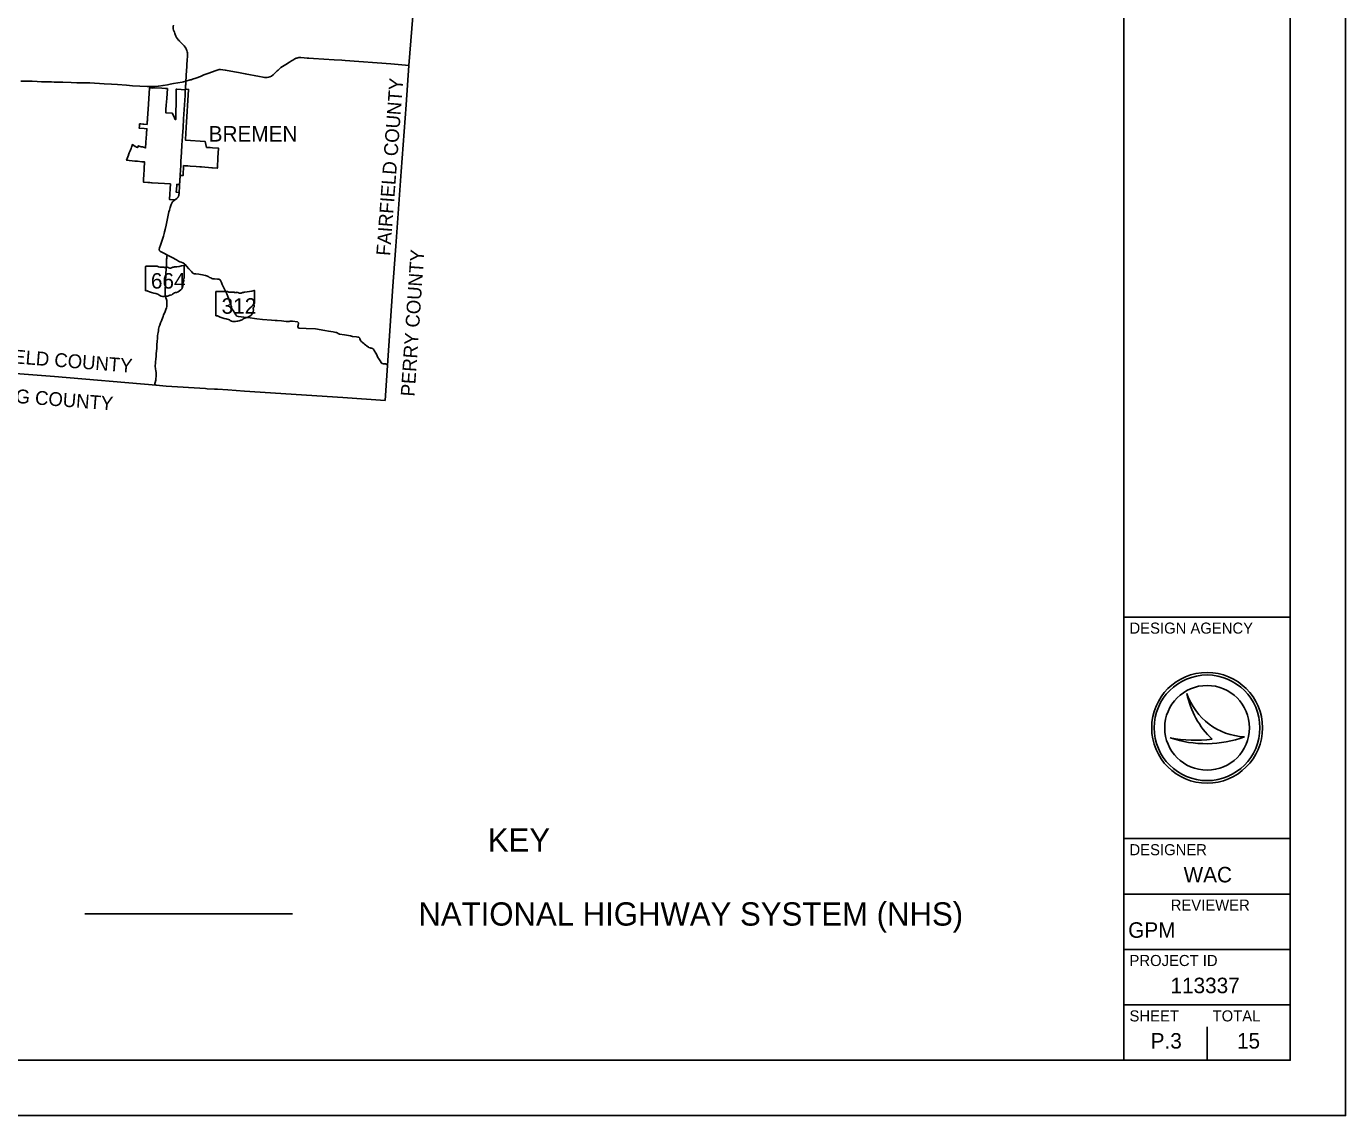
# Model space of a CAD drawing. Extents: x 1801177 to 2073177, y 551183 to 727183.
# Drawn here: x 1977949 to 2073177, y 551183 to 629829 of the extents above; entities that cross this region are included whole.
import ezdxf

# ---------------------------------------------------------------- set-up
doc = ezdxf.new("R2010")
doc.units = 0
for name, color, linetype in [('GM_X_Corporation', 7, 'Continuous'), ('GM_X_Corporation_Text', 7, 'Continuous'), ('GM_X_County', 7, 'Continuous'), ('GM_X_County_Text', 7, 'Continuous'), ('GM_X_State_Location', 7, 'Continuous'), ('GM_X_State_Route', 7, 'Continuous'), ('GM_X_State_Shield', 7, 'Continuous'), ('SH_Border', 7, 'Continuous'), ('SH_Cut_Line', 7, 'Continuous'), ('SH_Data', 7, 'Continuous'), ('UT_P_Electric', 7, 'Continuous')]:
    doc.layers.add(name, color=color, linetype=linetype)

msp = doc.modelspace()

# ---------------------------------------------------------------- linework, layer by layer
at = {"layer": 'GM_X_Corporation'}
msp.add_lwpolyline([(1988340, 618454), (1987024, 618539), (1986990, 618541), (1986971, 618542), (1986852, 618551), (1986707, 618561), (1986449, 618579), (1986419, 618581), (1986419, 618582), (1986419, 618584), (1986399, 618582), (1986403, 618671), (1986411, 618869), (1986422, 619030), (1986435, 619213), (1986449, 619392), (1986460, 619576), (1986485, 620013), (1986487, 620031), (1986487, 620037), (1986486, 620037), (1986322, 620051), (1986278, 620055), (1985970, 620085), (1985766, 620105), (1985183, 620162), (1985318, 620536), (1985324, 620550), (1985379, 620702), (1985400, 620757), (1985430, 620831), (1985481, 620962), (1985503, 621018), (1985534, 621099), (1985551, 621146), (1985608, 621296), (1985804, 621163), (1985817, 621155), (1985896, 621100), (1985982, 621117), (1985985, 621077), (1986020, 621206), (1986238, 621131), (1986336, 621122), (1986405, 621101), (1986553, 621055), (1986576, 621430), (1986604, 621816), (1986616, 622003), (1986621, 622074), (1986631, 622230), (1986635, 622283), (1986643, 622412), (1986645, 622432), (1986616, 622434), (1986450, 622447), (1986097, 622476), (1986106, 622631), (1986115, 622792), (1986203, 622785), (1986363, 622772), (1986377, 622771), (1986393, 622770), (1986424, 622767), (1986663, 622748), (1986669, 622848), (1986677, 622963), (1986681, 623028), (1986684, 623078), (1986691, 623191), (1986691, 623192), (1986713, 623504), (1986760, 624210), (1986840, 625392), (1986840, 625392), (1987076, 625371), (1987373, 625389), (1987727, 625366), (1987979, 625350), (1988128, 625341), (1988077, 624610), (1988044, 624129), (1988024, 623832), (1988007, 623587), (1988047, 623584), (1988443, 623557), (1988476, 623555), (1988483, 623554), (1988566, 623403), (1988565, 623385), (1988573, 623385), (1988580, 623384), (1988699, 623101), (1988713, 623100), (1988734, 623097), (1988734, 623097), (1988744, 623698), (1988752, 624221), (1988770, 625302), (1988770, 625302), (1988813, 625300), (1989427, 625258), (1989427, 625258), (1989429, 625282), (1989429, 625288), (1989499, 625285), (1989653, 625276), (1989653, 625276), (1989485, 622524), (1989431, 621653), (1989429, 621614), (1990857, 621511), (1990959, 621091), (1991227, 621072), (1991376, 621063), (1991380, 621062), (1991822, 621034), (1991780, 620340), (1991739, 619652), (1991725, 619590), (1991375, 619617), (1991332, 619620), (1990583, 619677), (1990483, 619683), (1990471, 619684), (1990195, 619705), (1989777, 619737), (1989765, 619738), (1989592, 619751), (1989580, 619752), (1989530, 619756), (1989518, 619757), (1989475, 619760), (1989414, 619765), (1989409, 619765), (1989389, 619767), (1989376, 619768), (1989299, 619774), (1989299, 619765), (1989296, 619711), (1989294, 619678), (1989292, 619654), (1989287, 619570), (1989286, 619543), (1989272, 619303), (1989262, 619134), (1989258, 619056), (1989133, 619066), (1989046, 619072), (1989025, 618707), (1989024, 618699), (1989021, 618640), (1989019, 618613), (1989018, 618595), (1989016, 618560), (1989012, 618501), (1989011, 618491), (1989008, 618440), (1989007, 618419), (1989007, 618411), (1988930, 618416), (1988807, 618424), (1988807, 618424), (1988803, 618365), (1988801, 618322), (1988772, 617855), (1988911, 617845), (1988971, 617841), (1988971, 617841), (1988966, 617749), (1988962, 617687), (1988962, 617685), (1988962, 617684), (1988962, 617684), (1988962, 617684), (1988962, 617683), (1988961, 617682), (1988961, 617682), (1988961, 617682), (1988961, 617681), (1988961, 617680), (1988961, 617679), (1988961, 617678), (1988958, 617649), (1988952, 617621), (1988944, 617593), (1988934, 617565), (1988922, 617539), (1988908, 617513), (1988892, 617489), (1988874, 617466), (1988854, 617445), (1988833, 617425), (1988811, 617406), (1988663, 617296), (1988268, 617331), (1988268, 617336), (1988270, 617362)], close=True, dxfattribs=at)
at = {"layer": 'GM_X_County'}
msp.add_lwpolyline([(2005845, 630559), (2005566, 627003), (2005354, 624172), (2005008, 619347), (2004609, 613967), (2004446, 611711), (2004409, 611078), (2004013, 605355), (2003837, 602826), (2000786, 603026), (1993695, 603490), (1992479, 603593), (1991738, 603625), (1991697, 603638), (1991650, 603642), (1991603, 603640), (1991519, 603633), (1990990, 603670), (1990885, 603680), (1990876, 603680), (1988048, 603860), (1987314, 603917), (1979976, 604550), (1972730, 605097)], dxfattribs=at)
at = {"layer": 'GM_X_State_Route'}
for p, q in [((1977541, 625881), (1977961, 625877)), ((1989461, 625868), (1989479, 626182)), ((1989461, 625868), (1989768, 625958)), ((1989422, 625245), (1989425, 625297))]:
    msp.add_line(p, q, dxfattribs=at)
for points in [[(1988973, 628804), (1988936, 628844), (1988860, 628936), (1988795, 629036), (1988744, 629118), (1988661, 629313), (1988629, 629400), (1988580, 629563), (1988556, 629650), (1988548, 629750), (1988549, 629823), (1988559, 629914)], [(1989479, 626182), (1989491, 626387), (1989501, 626535), (1989557, 627463), (1989569, 627608), (1989576, 627756), (1989578, 627831), (1989576, 627908), (1989562, 627987), (1989534, 628090), (1989514, 628144), (1989487, 628207), (1989460, 628255), (1989415, 628322), (1989340, 628419), (1989270, 628496), (1989097, 628664), (1989010, 628764), (1988973, 628804)], [(1990760, 626320), (1991054, 626437), (1991648, 626653), (1991795, 626701), (1991861, 626714), (1991958, 626718), (1992303, 626679), (1992578, 626627), (1992978, 626542), (1993262, 626487), (1993742, 626404), (1994778, 626200), (1995041, 626153), (1995146, 626138), (1995230, 626136), (1995323, 626140), (1995430, 626156), (1995520, 626188), (1995639, 626238), (1995759, 626330), (1995876, 626439), (1996046, 626609), (1996116, 626666), (1996242, 626785), (1996327, 626854), (1996556, 627004), (1996677, 627082), (1996934, 627245), (1997075, 627334), (1997171, 627392), (1997318, 627486), (1997424, 627524), (1997470, 627542), (1997622, 627575), (1997764, 627577), (1998012, 627568), (1998218, 627543), (1998348, 627539), (1998686, 627514), (2000176, 627419), (2000724, 627381), (2000957, 627367), (2004264, 627127), (2005568, 627001)], [(1977961, 625877), (1978358, 625861), (1978723, 625851), (1979030, 625836), (1979211, 625832), (1979766, 625822), (1979953, 625812), (1980585, 625802), (1981190, 625784), (1981601, 625764), (1982524, 625748), (1983553, 625692), (1984097, 625657), (1984527, 625624), (1985164, 625576), (1985604, 625547), (1986671, 625487), (1986961, 625482), (1987249, 625489), (1987464, 625504), (1987818, 625564), (1988127, 625612), (1988322, 625647), (1988573, 625695), (1989205, 625812)], [(1989205, 625812), (1989294, 625828), (1989461, 625868)], [(1989443, 625556), (1989449, 625639), (1989461, 625868)], [(1989768, 625958), (1989834, 625977), (1989928, 626008), (1990173, 626095), (1990506, 626219), (1990760, 626320)], [(1989223, 621917), (1989259, 622539), (1989300, 623160), (1989399, 624833), (1989422, 625245)], [(1989425, 625297), (1989426, 625307), (1989443, 625556)], [(1989200, 621555), (1989222, 621902), (1989223, 621917)], [(1989147, 620723), (1989182, 621270), (1989200, 621555)], [(1989094, 619840), (1989100, 619939), (1989107, 620048)], [(1989107, 620048), (1989132, 620451), (1989144, 620666), (1989147, 620723)], [(1989011, 618471), (1989017, 618581), (1989049, 619099), (1989091, 619787), (1989094, 619840)], [(1988103, 613327), (1988100, 613332), (1988096, 613338), (1988088, 613344), (1988077, 613352), (1988050, 613367), (1987924, 613433), (1987821, 613484), (1987675, 613553), (1987626, 613577), (1987607, 613589), (1987587, 613605), (1987571, 613620), (1987559, 613637), (1987549, 613654), (1987543, 613667), (1987539, 613680), (1987536, 613692), (1987535, 613707), (1987535, 613718), (1987535, 613732), (1987537, 613746), (1987541, 613762), (1987545, 613777), (1987550, 613795), (1987564, 613843), (1987627, 614030), (1987723, 614309), (1987798, 614543), (1987841, 614684), (1987894, 614874), (1987927, 615001), (1987963, 615161), (1988029, 615466), (1988130, 615964), (1988206, 616317), (1988233, 616429), (1988268, 616556), (1988330, 616760), (1988371, 616885), (1988398, 616962), (1988417, 617008), (1988439, 617053), (1988463, 617096), (1988481, 617124), (1988500, 617151), (1988522, 617176), (1988545, 617200), (1988582, 617232), (1988634, 617272), (1988780, 617379), (1988818, 617410), (1988853, 617442), (1988865, 617455), (1988876, 617466), (1988896, 617492), (1988913, 617519), (1988920, 617534), (1988927, 617548), (1988939, 617579), (1988947, 617610), (1988951, 617626), (1988954, 617642), (1988961, 617690), (1988970, 617788), (1988974, 617838), (1988980, 617935), (1988993, 618171), (1989011, 618471)], [(1987315, 603915), (1987269, 603938), (1987241, 603965), (1987230, 603990), (1987228, 604014), (1987230, 604049), (1987241, 604106), (1987288, 604280), (1987305, 604419), (1987312, 604529), (1987319, 604638), (1987317, 604726), (1987308, 604830), (1987294, 604958), (1987281, 605094), (1987255, 605303), (1987252, 605367), (1987260, 605469), (1987277, 605619), (1987297, 605805), (1987315, 606011), (1987327, 606199), (1987344, 606369), (1987358, 606600), (1987374, 606853), (1987394, 607079), (1987404, 607325), (1987418, 607479), (1987446, 607627), (1987468, 607734), (1987481, 607847), (1987493, 607969), (1987508, 608058), (1987541, 608163), (1987570, 608257), (1987641, 608418), (1987692, 608564), (1987787, 608826), (1987814, 608892), (1987854, 608995), (1987913, 609123), (1987973, 609251), (1988023, 609390), (1988062, 609514), (1988082, 609594), (1988087, 609656), (1988088, 609761), (1988095, 609983), (1988095, 610012), (1988087, 610046), (1988067, 610099), (1988016, 610235), (1987994, 610309), (1987983, 610359), (1987976, 610405), (1987971, 610511), (1987975, 610712), (1987974, 610888), (1987989, 611159), (1987991, 611415), (1988009, 611849), (1988047, 612438), (1988056, 612599), (1988062, 612884), (1988074, 613032), (1988085, 613096), (1988097, 613211), (1988106, 613282), (1988107, 613312), (1988103, 613327)], [(1997584, 608428), (1997554, 608465), (1997510, 608488), (1997163, 608541), (1997034, 608543), (1996972, 608537), (1996936, 608522), (1996867, 608519), (1996691, 608530), (1996361, 608557), (1996057, 608587), (1995917, 608597), (1995642, 608616), (1994985, 608667), (1994579, 608714), (1993932, 608801), (1993655, 608835), (1993255, 608880), (1993148, 608899), (1993071, 609012), (1993000, 609129), (1992882, 609319), (1992806, 609417), (1992763, 609494), (1992748, 609569), (1992738, 609656), (1992712, 609741), (1992684, 609815), (1992641, 609938), (1992584, 610078), (1992484, 610328), (1992408, 610523), (1992317, 610703), (1992247, 610858), (1992085, 611191), (1992022, 611348), (1991989, 611423), (1991937, 611518), (1991898, 611554), (1991870, 611571), (1991829, 611583), (1991748, 611587), (1991524, 611599), (1991403, 611610), (1991340, 611625), (1991255, 611665), (1991178, 611705), (1991112, 611743), (1991029, 611782), (1990873, 611840), (1990749, 611873), (1990669, 611887), (1990512, 611911), (1990399, 611926), (1990172, 611950), (1990063, 611967), (1990034, 611975), (1990005, 611986), (1989970, 612006), (1989938, 612033), (1989857, 612127), (1989668, 612330), (1989502, 612525), (1989408, 612627), (1989354, 612681), (1989320, 612710), (1989287, 612732), (1989241, 612754), (1989117, 612803), (1989026, 612839), (1988940, 612880), (1988775, 612967), (1988475, 613138), (1988139, 613318), (1988120, 613324), (1988103, 613327)], [(1997536, 608085), (1997554, 608158), (1997572, 608241), (1997587, 608396), (1997584, 608428)], [(2001195, 607500), (2000917, 607550), (2000562, 607611), (2000504, 607629), (2000462, 607648), (2000382, 607693), (2000325, 607719), (2000280, 607732), (2000086, 607776), (1999746, 607834), (1999492, 607879), (1999090, 607945), (1998961, 607965), (1998816, 607988), (1998142, 608016), (1997648, 608046), (1997584, 608059), (1997536, 608085)], [(2001487, 607446), (2001345, 607476), (2001195, 607500)], [(2004014, 605352), (2003915, 605436), (2003866, 605457), (2003851, 605463), (2003827, 605469), (2003802, 605472), (2003753, 605474), (2003705, 605474), (2003673, 605476), (2003647, 605480), (2003626, 605483), (2003594, 605500), (2003553, 605551), (2003475, 605689), (2003402, 605816), (2003330, 605931), (2003215, 606150), (2003165, 606240), (2003065, 606425), (2003032, 606480), (2003004, 606516), (2002980, 606544), (2002969, 606555), (2002949, 606564), (2002914, 606575), (2002880, 606586), (2002816, 606599), (2002755, 606613), (2002672, 606645), (2002641, 606660), (2002545, 606729), (2002494, 606773), (2002441, 606818), (2002367, 606886), (2002301, 606934), (2002217, 606997), (2002152, 607049), (2002118, 607083), (2002093, 607118), (2002054, 607200), (2002026, 607274), (2002012, 607316), (2001994, 607351), (2001970, 607372), (2001946, 607381), (2001875, 607391), (2001771, 607406), (2001487, 607446)]]:
    msp.add_lwpolyline(points, dxfattribs=at)
at = {"layer": 'GM_X_State_Shield'}
for p, q in [((1986542, 612475), (1986542, 610774)), ((1987390, 612505), (1986569, 612505)), ((1989343, 611657), (1989343, 612547)), ((1989343, 611657), (1989343, 611657)), ((1991623, 610661), (1991623, 608960)), ((1992471, 610690), (1991651, 610690)), ((1994425, 609843), (1994425, 610732)), ((1994425, 609843), (1994425, 609843))]:
    msp.add_line(p, q, dxfattribs=at)
for centre, major_axis, start_param, end_param in [((1986574, 612479), (32.5, 0), 1.712693, 3.28349), ((1987585, 612702), (315, 0), 4.042523, 4.731795), ((1987689, 611550), (1130, 0), 1.404758, 1.657858), ((1987946, 612488), (90.8, 0), 3.836095, 5.185415), ((1988079, 612291), (189, 0), 0.950623, 2.079405), ((1988323, 612561), (227, 0), 4.081561, 5.145723), ((1988724, 611985), (598, 0), 1.699011, 2.107814), ((1988345, 614824), (2971, 0), 4.814394, 5.042369), ((1989312, 612551), (31.2, 0), 6.141152, 7.989035), ((1989455, 611285), (211, 0), 2.387724, 3.262537), ((1989336, 611592), (48.3, 0), 1.883978, 3.671073), ((1989029, 611479), (290, 0), 5.934695, 6.695948), ((1989310, 611654), (33.4, 0), 5.05454, 6.418171), ((1986574, 610771), (32.7, 0), 3.00124, 4.508301), ((1986579, 610945), (250, 0), 4.665946, 4.897461), ((1986630, 610676), (90.1, 0), 0.519207, 1.627899), ((1987768, 612205), (2146, 0), 4.195997, 4.488961), ((1987128, 610010), (671, 0), 0.823519, 1.323587), ((1988131, 610540), (227, 0), 4.691044, 5.507374), ((1988337, 610376), (63.9, 0), 1.147584, 2.315152), ((1988309, 610609), (240, 0), 4.937069, 5.64225), ((1988825, 610297), (407, 0), 1.647645, 2.488434), ((1988512, 611171), (743, 0), 5.101752, 6.440018), ((1991655, 610665), (32.5, 0), 1.712693, 3.28349), ((1992667, 610888), (315, 0), 4.042523, 4.731795), ((1992771, 609735), (1130, 0), 1.404758, 1.657858), ((1993028, 610673), (90.8, 0), 3.836095, 5.185415), ((1993161, 610477), (189, 0), 0.950623, 2.079405), ((1993405, 610747), (227, 0), 4.081561, 5.145723), ((1993806, 610171), (598, 0), 1.699011, 2.107814), ((1993427, 613010), (2971, 0), 4.814394, 5.042369), ((1994394, 610736), (31.2, 0), 6.141152, 7.989035), ((1987854, 610668), (426, 0), 4.026481, 4.996735), ((1988100, 610080), (350, 0), 1.495662, 1.94098), ((1994537, 609470), (211, 0), 2.387724, 3.262537), ((1994418, 609777), (48.3, 0), 1.883978, 3.671073), ((1994111, 609665), (290, 0), 5.934695, 6.695948), ((1994392, 609839), (33.4, 0), 5.05454, 6.418171), ((1991656, 608956), (32.7, 0), 3.00124, 4.508301), ((1991661, 609130), (250, 0), 4.665946, 4.897461), ((1991712, 608862), (90.1, 0), 0.519207, 1.627899), ((1992849, 610390), (2146, 0), 4.195997, 4.488961), ((1992210, 608196), (671, 0), 0.823519, 1.323587), ((1992936, 608853), (426, 0), 4.026481, 4.996735), ((1993182, 608265), (350, 0), 1.495662, 1.94098), ((1993213, 608726), (227, 0), 4.691044, 5.507374), ((1993418, 608561), (63.9, 0), 1.147584, 2.315152), ((1993391, 608795), (240, 0), 4.937069, 5.64225), ((1993907, 608482), (407, 0), 1.647645, 2.488434), ((1993593, 609357), (743, 0), 5.101752, 6.440018)]:
    msp.add_ellipse(centre, major_axis=major_axis, ratio=0.8, start_param=start_param, end_param=end_param, dxfattribs=at)
at = {"layer": 'SH_Border'}
for p, q in [((2057177, 555183), (2057177, 723183)), ((2057177, 587183), (2069177, 587183)), ((2057177, 571183), (2069177, 571183)), ((2057177, 567183), (2069177, 567183)), ((2057177, 563183), (2069177, 563183)), ((2057177, 559183), (2069177, 559183))]:
    msp.add_line(p, q, dxfattribs=at)
msp.add_lwpolyline([(1813177, 723183), (2069177, 723183), (2069177, 555183), (1813177, 555183)], close=True, dxfattribs=at)
at = {"layer": 'SH_Cut_Line'}
msp.add_lwpolyline([(1801177, 551183), (2073177, 551183), (2073177, 727183), (1801177, 727183)], close=True, dxfattribs=at)
at = {"layer": 'SH_Data'}
for p, q in [((2061717, 581660), (2061717, 581660)), ((2063177, 579183), (2063177, 579183)), ((2060514, 578459), (2060514, 578459)), ((2065875, 578531), (2065875, 578531)), ((2063177, 555183), (2063177, 557583)), ((2060177, 556583), (2060177, 556583))]:
    msp.add_line(p, q, dxfattribs=at)
for radius in [4000, 3814, 3814, 3058]:
    msp.add_circle((2063177, 579183), radius, dxfattribs=at)
for centre, radius, start, end in [((2066105, 583164), 4639, 198.92567, 198.93195), ((2067950, 582944), 6365, 191.63793, 191.64215), ((2066105, 583164), 4639, 198.93195, 267.16574), ((2067950, 582944), 6365, 191.64215, 226.09467), ((2062361, 588418), 10128, 259.49639, 259.49952), ((2063092, 586143), 8105, 251.45274, 251.45764), ((2063092, 586143), 8105, 251.45764, 290.08324), ((2062361, 588418), 10128, 259.49952, 276.66723)]:
    msp.add_arc(centre, radius, start, end, dxfattribs=at)
at = {"layer": 'UT_P_Electric'}
msp.add_line((1982166, 565743), (1997166, 565743), dxfattribs=at)

# ---------------------------------------------------------------- texts
at = {"layer": 'GM_X_Corporation_Text'}
msp.add_text('BREMEN', height=1120, rotation=0.00001, dxfattribs=at).set_placement((1991106, 621512))
at = {"layer": 'GM_X_County_Text'}
for s, rotation, p in [('FAIRFIELD COUNTY', 85.68928, (2004198, 613239)), ('PERRY COUNTY', 86.11607, (2005964, 603085)), ('FAIRFIELD COUNTY', 355.46053, (1972751, 605838)), ('HOCKING COUNTY', 355.51045, (1971952, 603053))]:
    msp.add_text(s, height=1000, rotation=rotation, dxfattribs=at).set_placement(p)
at = {"layer": 'GM_X_State_Location'}
for s, p in [('664', (1987621, 612136)), ('312', (1992395, 609391))]:
    msp.add_text(s, height=1, rotation=0.00001, dxfattribs=at).set_placement(p)
for s, p in [('s', (1987974, 612209)), ('r', (1987974, 612209)), ('s', (1992748, 609463)), ('r', (1992748, 609463))]:
    msp.add_text(s, height=1, dxfattribs=at).set_placement(p)
at = {"layer": 'GM_X_State_Shield'}
for s, p in [('664', (1986937, 610894)), ('312', (1992040, 609080))]:
    msp.add_text(s, height=1120.7, dxfattribs=at).set_placement(p)
at = {"layer": 'SH_Data'}
for s, height, p in [('DESIGN AGENCY', 800, (2057577, 585983)), ('DESIGNER', 800, (2057577, 569983)), ('WAC', 1120, (2061481, 568023)), ('REVIEWER', 800, (2060552, 565983)), ('GPM', 1120, (2057484, 564023)), ('PROJECT ID', 800, (2057577, 561983)), ('113337', 1120, (2060536, 560023)), ('SHEET', 800, (2057577, 557983)), ('TOTAL', 800, (2063577, 557983)), ('P.3', 1120, (2059105, 556023)), ('15', 1120, (2065335, 556023))]:
    msp.add_text(s, height=height, dxfattribs=at).set_placement(p)
at = {"layer": 'UT_P_Electric'}
for s, p in [('KEY', (2011259, 570251)), ('NATIONAL HIGHWAY SYSTEM (NHS)', (2006246, 564903))]:
    msp.add_text(s, height=1680, dxfattribs=at).set_placement(p)

doc.saveas('drawing.dxf')
